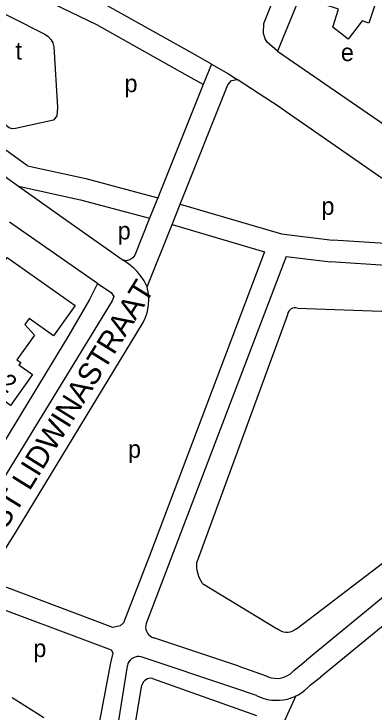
# Model space of a CAD drawing. Extents: x 162804 to 165059, y 381530 to 382901.
# Drawn here: x 163085.6 to 163167.6, y 381854.4 to 382013.3 of the extents above; entities that cross this region are included whole.
import ezdxf

# ---------------------------------------------------------------- set-up
doc = ezdxf.new("R2010")
doc.units = 0
for name, color, linetype in [('BLT_Basislijn', 7, 'Continuous'), ('BLT_Bebouwing', 7, 'Continuous'), ('BLT_Centroide', 7, 'Continuous'), ('BLT_Huisnummer', 7, 'Continuous'), ('BLT_Straatnaam', 7, 'Continuous')]:
    doc.layers.add(name, color=color, linetype=linetype)

msp = doc.modelspace()

# ---------------------------------------------------------------- linework, layer by layer
at = {"layer": 'BLT_Basislijn'}
for p, q in [((163152.26, 381987.77), (163147.39, 381991.15)), ((163182.22, 381966.95), (163152.26, 381987.77)), ((163104.58, 381951.95), (163084.55, 381965.91)), ((163178.98, 381960.46), (163158.11, 381961.82)), ((163147.57, 381958.05), (163115.71, 381874.52)), ((163178.93, 381955.45), (163157.66, 381956.84)), ((163150.19, 381946.33), (163177.8, 381945.3)), ((163147.87, 381944.78), (163127.22, 381888.49)), ((163083.34, 381891.02), (163086.18, 381895.57)), ((163149.93, 381873.26), (163177.55, 381894.43)), ((163179.83, 381888.87), (163152.22, 381866.15)), ((163186.47, 381887.86), (163155.39, 381862.29)), ((163128.51, 381883.59), (163145.55, 381873.26)), ((163136.79, 381864.79), (163117.43, 381871.24)), ((163135.21, 381860.04), (163115, 381866.78)), ((163149.34, 381863.8), (163152.22, 381866.15)), ((163111.36, 381864.76), (163102.93, 381812.19)), ((163136.79, 381864.79), (163143.06, 381862.58)), ((163117.16, 381861.98), (163140.79, 381853.59)), ((163153.11, 381860.51), (163155.39, 381862.29)), ((163112.85, 381849.67), (163114.7, 381860.45)), ((163140.81, 381858.11), (163135.21, 381860.04)), ((163149.81, 381858.03), (163123.07, 381800.56)), ((163085.15, 381857.68), (163092.38, 381853.12))]:
    msp.add_line(p, q, dxfattribs=at)
for points in [[(163145.62, 382004.79), (163143.27, 382006.86), (163142.81, 382007.62), (163142.4, 382008.87), (163142.53, 382011.16), (163151.68, 382034.27), (163152.64, 382035.87), (163153.2, 382036.38), (163155.67, 382037.77), (163157.88, 382037.75), (163170.3, 382034.11), (163180.94, 382030.69), (163181.72, 382030.43)], [(163163.06, 382032.1), (163158.5, 382033.39), (163157.74, 382033.36), (163156.44, 382031.34), (163145.62, 382004.79)], [(163069.06, 382020.59), (163092.61, 382008.67), (163093.4, 382008.13), (163093.97, 382007.5), (163094.42, 382006.7), (163094.66, 382005.84), (163095.46, 381992), (163095.33, 381990.1), (163094.6, 381989.08), (163085.95, 381987.21), (163085.18, 381987.15), (163084.46, 381987.37), (163083.85, 381987.84), (163083.46, 381988.49), (163073.39, 382007.47), (163072.87, 382008.21), (163072.1, 382008.69), (163021.58, 382030.69)], [(163130.58, 382001.9), (163126.98, 382003.89), (163106.74, 382015.23), (163088.97, 382023.89)], [(163128.71, 381997.23), (163124.55, 381999.52), (163104.42, 382010.79), (163086.74, 382019.42)], [(163145.62, 382004.79), (163166.07, 381990.82), (163226.4, 381949.49)], [(163130.58, 382001.9), (163128.71, 381997.23)], [(163130.58, 382001.9), (163134.44, 381999.67), (163136.42, 381998.4)], [(163123.46, 381970), (163134.33, 381997.16), (163135.16, 381998.14), (163136.42, 381998.4)], [(163147.39, 381991.15), (163146.22, 381991.96), (163136.42, 381998.4)], [(163128.71, 381997.23), (163118.35, 381971.44)], [(163088.69, 381978.74), (163083.72, 381982.26)], [(163079.98, 381978.78), (163086.6, 381974.08)], [(163088.69, 381978.74), (163101.93, 381975.86), (163118.35, 381971.44)], [(163086.6, 381974.08), (163097.81, 381966.12), (163110.46, 381957.2)], [(163086.6, 381974.08), (163100.75, 381971), (163116.47, 381966.77)], [(163118.35, 381971.44), (163116.47, 381966.77)], [(163121.59, 381965.34), (163123.46, 381970)], [(163123.46, 381970), (163146.49, 381963.21), (163158.11, 381961.82)], [(163116.47, 381966.77), (163113.11, 381958.38), (163112.64, 381957.74), (163112, 381957.31), (163111.22, 381957.12), (163110.46, 381957.2)], [(163115.91, 381951.14), (163121.59, 381965.34)], [(163121.59, 381965.34), (163142.62, 381959.14)], [(163142.62, 381959.14), (163116.47, 381889.89), (163110.52, 381874.65), (163109.75, 381873.99), (163108.12, 381873.63), (163079.23, 381884.44)], [(163115.91, 381951.14), (163115.22, 381952.51), (163114.55, 381953.55), (163113.65, 381954.65), (163112.87, 381955.42), (163111.73, 381956.34), (163110.46, 381957.2)], [(163147.57, 381958.05), (163157.66, 381956.84)], [(163104.58, 381951.95), (163107.72, 381949.86), (163108.33, 381948.97), (163107.96, 381947.96), (163081.42, 381904.82), (163078.3, 381900.84), (163076.07, 381900.06), (163074.79, 381900.06), (163072.4, 381900.61), (163058.73, 381911.86), (163052.24, 381916.83)], [(163104.58, 381951.95), (163102.76, 381948.29), (163098.1, 381940.15), (163076.45, 381904.65), (163075.65, 381904.65), (163073.11, 381906.41), (163055.05, 381920.69)], [(163086.18, 381895.57), (163114.98, 381943.02), (163115.47, 381944.05), (163115.89, 381945.27), (163116.16, 381946.5), (163116.3, 381948.02), (163116.23, 381949.52), (163115.91, 381951.14)], [(163150.19, 381946.33), (163149.81, 381946.39), (163149.43, 381946.38), (163149.06, 381946.29), (163148.72, 381946.12), (163148.42, 381945.88), (163148.17, 381945.59), (163147.99, 381945.25), (163147.88, 381944.89), (163147.87, 381944.78)], [(163128.51, 381883.59), (163128.11, 381884.28), (163127.78, 381885.01), (163127.52, 381885.78), (163127.34, 381886.56), (163127.23, 381887.36), (163127.21, 381888.16), (163127.22, 381888.49)], [(163104.6, 381849.45), (163107.64, 381865.58), (163108.17, 381867.76), (163107.76, 381868.42), (163076.53, 381880.11)], [(163115.71, 381874.52), (163115.6, 381874.08), (163115.57, 381873.63), (163115.62, 381873.18), (163115.76, 381872.75), (163115.96, 381872.34), (163116.23, 381871.98), (163116.57, 381871.68), (163116.95, 381871.43), (163117.43, 381871.24)], [(163149.93, 381873.26), (163149.5, 381872.96), (163149.02, 381872.73), (163148.52, 381872.57), (163148, 381872.49), (163147.47, 381872.49), (163146.95, 381872.57), (163146.45, 381872.73), (163145.97, 381872.96), (163145.55, 381873.26)], [(163115, 381866.78), (163114.56, 381866.92), (163114.11, 381866.98), (163113.65, 381866.96), (163113.2, 381866.87), (163112.77, 381866.7), (163112.38, 381866.45), (163112.04, 381866.14), (163111.76, 381865.78), (163111.54, 381865.38), (163111.4, 381864.94), (163111.36, 381864.76)], [(163143.06, 381862.58), (163143.65, 381862.32), (163144.27, 381862.15), (163144.91, 381862.04), (163145.56, 381862.02), (163146.2, 381862.08), (163146.83, 381862.22), (163147.44, 381862.43), (163148.02, 381862.72), (163148.56, 381863.07), (163149.05, 381863.49), (163149.34, 381863.8)], [(163117.16, 381861.98), (163116.76, 381862.03), (163116.36, 381862), (163115.96, 381861.9), (163115.6, 381861.72), (163115.28, 381861.47), (163115.02, 381861.16), (163114.82, 381860.81), (163114.7, 381860.45)], [(163149.81, 381858.03), (163150.37, 381858.3), (163151.14, 381858.77), (163151.87, 381859.31), (163152.54, 381859.91), (163153.11, 381860.51)], [(163140.81, 381858.11), (163141.63, 381857.74), (163142.49, 381857.45), (163143.36, 381857.23), (163144.26, 381857.09), (163145.16, 381857.02), (163146.06, 381857.04), (163146.96, 381857.14), (163147.85, 381857.31), (163148.72, 381857.57), (163149.56, 381857.9), (163149.81, 381858.03)]]:
    msp.add_lwpolyline(points, dxfattribs=at)
at = {"layer": 'BLT_Bebouwing'}
for points in [[(163177.59, 382017.54), (163169.4, 382020.23), (163166.44, 382011.21), (163164.92, 382011.71), (163164.43, 382011.11), (163161.72, 382007.59), (163158.19, 382010.3), (163159.52, 382014.36), (163156.25, 382015.44), (163158.92, 382023.55), (163158.7, 382023.62), (163159.71, 382026.7), (163161.14, 382026.23), (163163.06, 382032.1)], [(163081.13, 381953.8), (163084.02, 381957.88), (163099.49, 381946.89), (163094.58, 381939.99), (163089.01, 381943.94), (163088.04, 381942.58), (163090.27, 381940.19), (163086.26, 381934.55), (163087.11, 381933.96), (163086.69, 381933.37), (163089.8, 381931.17), (163084.81, 381924.15), (163081.65, 381926.39)]]:
    msp.add_lwpolyline(points, dxfattribs=at)

# ---------------------------------------------------------------- texts
at = {"layer": 'BLT_Centroide'}
for s, p in [('t', (163085.91, 382002.91)), ('e', (163160.04, 382002.56)), ('p', (163110.75, 381995.49)), ('p', (163155.61, 381967.56)), ('p', (163109.2, 381961.96)), ('p', (163111.54, 381912.24)), ('p', (163089.98, 381866.87))]:
    msp.add_text(s, height=4, dxfattribs=at).set_placement(p)
at = {"layer": 'BLT_Huisnummer'}
msp.add_text('2', height=4, rotation=324.6122, dxfattribs=at).set_placement((163081.94, 381928.51))
at = {"layer": 'BLT_Straatnaam'}
msp.add_text('ST LIDWINASTRAAT', height=5, rotation=58.1784, dxfattribs=at).set_placement((163083.63, 381895.69))

doc.saveas('drawing.dxf')
